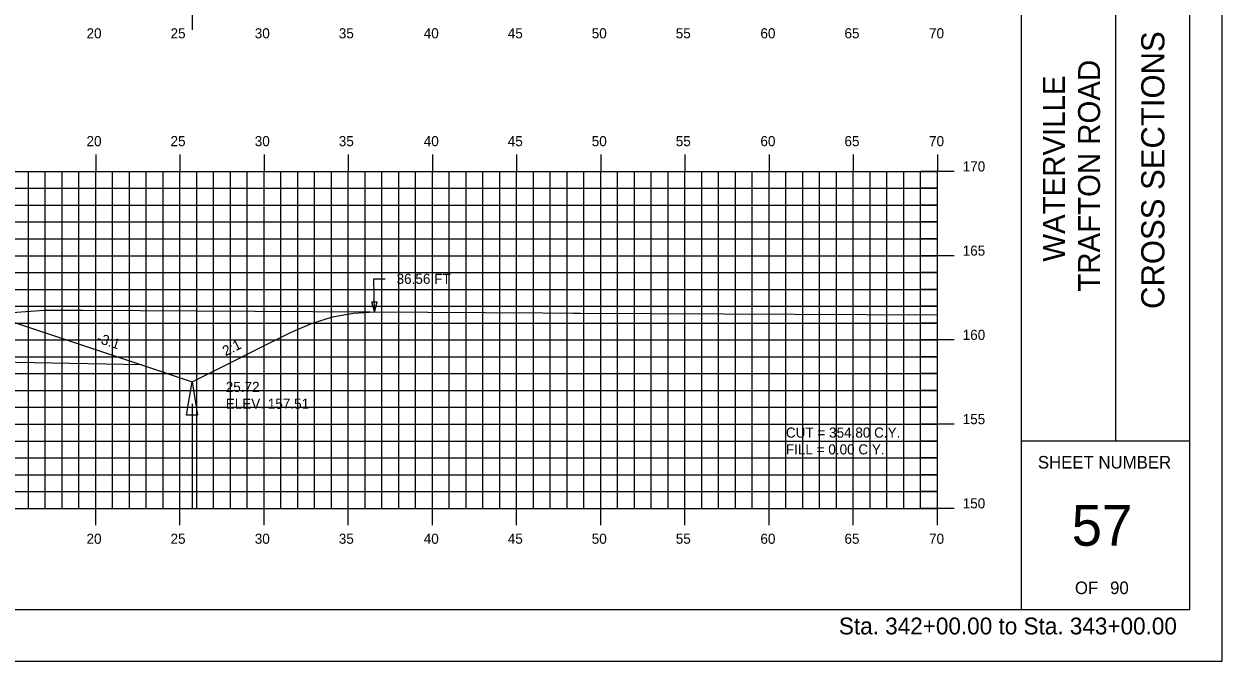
# Model space of a CAD drawing. Extents: x 1143198 to 1143368, y 608981 to 609091.
# Drawn here: x 1143297.1 to 1143368.2, y 608981.3 to 609019.1 of the extents above; entities that cross this region are included whole.
import ezdxf

# ---------------------------------------------------------------- set-up
doc = ezdxf.new("R2010")
doc.units = 0
for name, color, linetype in [('ANNOTATION', 7, 'Continuous'), ('BORDER', 7, 'Continuous'), ('D_Drainage_Ditch_Line', 7, 'Continuous'), ('D_Roadway_SlopeLines', 7, 'Continuous'), ('D_Roadway_SubGrade', 7, 'Continuous'), ('D_Text_Standard', 7, 'Continuous'), ('H_V ANNOTATION', 7, 'Continuous'), ('HIGHWAY_TITLE', 7, 'Continuous'), ('MAJOR', 7, 'Continuous'), ('MINOR', 7, 'Continuous'), ('PLOT BOUNDARY', 7, 'Continuous'), ('S_Roadway_Centerline', 7, 'Continuous')]:
    doc.layers.add(name, color=color, linetype=linetype)

msp = doc.modelspace()

# ---------------------------------------------------------------- linework, layer by layer
msp.add_lwpolyline([(1143243.539, 609002.652), (1143244.789, 609002.562), (1143246.039, 609002.32), (1143247.289, 609001.925), (1143248.539, 609001.376), (1143255.598, 608997.847), (1143258.598, 608998.847), (1143266.322, 609001.421), (1143266.323, 609001.421), (1143270.323, 609001.581), (1143281.323, 609001.801), (1143292.323, 609001.581), (1143296.323, 609001.421), (1143304.047, 608998.847), (1143307.047, 608997.847), (1143312.886, 609000.767), (1143314.136, 609001.313), (1143315.386, 609001.7), (1143316.636, 609001.93), (1143317.886, 609002.001)])
at = {"layer": 'BORDER'}
for p, q in [((1143356.323, 608984.335), (1143356.323, 609089.335)), ((1143361.914, 608994.338), (1143361.914, 609029.338)), ((1143356.323, 608994.338), (1143366.323, 608994.338))]:
    msp.add_line(p, q, dxfattribs=at)
msp.add_lwpolyline([(1143206.323, 608984.335), (1143366.323, 608984.335), (1143366.323, 609089.335), (1143206.323, 609089.335)], close=True, dxfattribs=at)
at = {"layer": 'D_Drainage_Ditch_Line'}
for p, q in [((1143307.047, 609024.984), (1143307.046, 609018.741)), ((1143307.047, 608996.535), (1143307.046, 608990.291))]:
    msp.add_line(p, q, dxfattribs=at)
msp.add_lwpolyline([(1143307.375, 608995.878), (1143306.718, 608995.878), (1143307.047, 608997.847)], close=True, dxfattribs=at)
at = {"layer": 'D_Roadway_SlopeLines'}
for points in [[(1143307.047, 608997.847), (1143312.886, 609000.767), (1143314.136, 609001.313), (1143315.386, 609001.7), (1143316.636, 609001.93), (1143317.886, 609002.001)], [(1143304.047, 608998.847), (1143307.047, 608997.847)]]:
    msp.add_lwpolyline(points, dxfattribs=at)
at = {"layer": 'D_Roadway_SubGrade'}
msp.add_lwpolyline([(1143292.323, 609001.165), (1143292.323, 609001.331), (1143296.323, 609001.171), (1143296.323, 609001.421), (1143296.323, 609001.421), (1143304.047, 608998.847), (1143292.323, 608999.081)], close=True, dxfattribs=at)
at = {"layer": 'D_Text_Standard'}
msp.add_lwpolyline([(1143317.886, 609002.017), (1143317.837, 609003.964), (1143318.517, 609003.964)], dxfattribs=at)
msp.add_lwpolyline([(1143317.886, 609002.017), (1143317.726, 609002.595), (1143318.017, 609002.602)], close=True, dxfattribs=at)
at = {"layer": 'MAJOR'}
for p, q in [((1143301.323, 609011.337), (1143301.323, 609010.335)), ((1143306.323, 609011.337), (1143306.323, 609010.335)), ((1143311.323, 609011.337), (1143311.323, 609010.335)), ((1143316.323, 609011.337), (1143316.323, 609010.335)), ((1143321.323, 609011.337), (1143321.323, 609010.335)), ((1143326.323, 609011.337), (1143326.323, 609010.335)), ((1143331.323, 609011.337), (1143331.323, 609010.335)), ((1143336.323, 609011.337), (1143336.323, 609010.335)), ((1143341.323, 609011.337), (1143341.323, 609010.335)), ((1143346.323, 609011.337), (1143346.323, 609010.335)), ((1143351.323, 609011.337), (1143351.323, 609010.335)), ((1143211.323, 609010.335), (1143351.323, 609010.335)), ((1143211.323, 609010.335), (1143351.323, 609010.335)), ((1143301.323, 608990.335), (1143301.323, 609010.335)), ((1143306.323, 608990.335), (1143306.323, 609010.335)), ((1143311.323, 608990.335), (1143311.323, 609010.335)), ((1143316.323, 608990.335), (1143316.323, 609010.335)), ((1143321.323, 608990.335), (1143321.323, 609010.335)), ((1143326.323, 608990.335), (1143326.323, 609010.335)), ((1143331.323, 608990.335), (1143331.323, 609010.335)), ((1143336.323, 608990.335), (1143336.323, 609010.335)), ((1143341.323, 608990.335), (1143341.323, 609010.335)), ((1143346.323, 608990.335), (1143346.323, 609010.335)), ((1143352.325, 609010.335), (1143350.321, 609010.335)), ((1143351.323, 608990.335), (1143351.323, 609010.335)), ((1143351.323, 608990.335), (1143351.323, 609010.335)), ((1143211.323, 609005.335), (1143351.323, 609005.335)), ((1143352.325, 609005.335), (1143350.321, 609005.335)), ((1143211.323, 609000.335), (1143351.323, 609000.335)), ((1143352.325, 609000.335), (1143350.321, 609000.335)), ((1143211.323, 608995.335), (1143351.323, 608995.335)), ((1143352.325, 608995.335), (1143350.321, 608995.335)), ((1143211.323, 608990.335), (1143351.323, 608990.335)), ((1143211.323, 608990.335), (1143351.323, 608990.335)), ((1143301.323, 608989.333), (1143301.323, 608990.335)), ((1143306.323, 608989.333), (1143306.323, 608990.335)), ((1143311.323, 608989.333), (1143311.323, 608990.335)), ((1143316.323, 608989.333), (1143316.323, 608990.335)), ((1143321.323, 608989.333), (1143321.323, 608990.335)), ((1143326.323, 608989.333), (1143326.323, 608990.335)), ((1143331.323, 608989.333), (1143331.323, 608990.335)), ((1143336.323, 608989.333), (1143336.323, 608990.335)), ((1143341.323, 608989.333), (1143341.323, 608990.335)), ((1143346.323, 608989.333), (1143346.323, 608990.335)), ((1143352.325, 608990.335), (1143350.321, 608990.335)), ((1143351.323, 608989.333), (1143351.323, 608990.335))]:
    msp.add_line(p, q, dxfattribs=at)
at = {"layer": 'MINOR'}
for p, q in [((1143297.323, 608990.335), (1143297.323, 609010.335)), ((1143298.323, 608990.335), (1143298.323, 609010.335)), ((1143299.323, 608990.335), (1143299.323, 609010.335)), ((1143300.323, 608990.335), (1143300.323, 609010.335)), ((1143302.323, 608990.335), (1143302.323, 609010.335)), ((1143303.323, 608990.335), (1143303.323, 609010.335)), ((1143304.323, 608990.335), (1143304.323, 609010.335)), ((1143305.323, 608990.335), (1143305.323, 609010.335)), ((1143307.323, 608990.335), (1143307.323, 609010.335)), ((1143308.323, 608990.335), (1143308.323, 609010.335)), ((1143309.323, 608990.335), (1143309.323, 609010.335)), ((1143310.323, 608990.335), (1143310.323, 609010.335)), ((1143312.323, 608990.335), (1143312.323, 609010.335)), ((1143313.323, 608990.335), (1143313.323, 609010.335)), ((1143314.323, 608990.335), (1143314.323, 609010.335)), ((1143315.323, 608990.335), (1143315.323, 609010.335)), ((1143317.323, 608990.335), (1143317.323, 609010.335)), ((1143318.323, 608990.335), (1143318.323, 609010.335)), ((1143319.323, 608990.335), (1143319.323, 609010.335)), ((1143320.323, 608990.335), (1143320.323, 609010.335)), ((1143322.323, 608990.335), (1143322.323, 609010.335)), ((1143323.323, 608990.335), (1143323.323, 609010.335)), ((1143324.323, 608990.335), (1143324.323, 609010.335)), ((1143325.323, 608990.335), (1143325.323, 609010.335)), ((1143327.323, 608990.335), (1143327.323, 609010.335)), ((1143328.323, 608990.335), (1143328.323, 609010.335)), ((1143329.323, 608990.335), (1143329.323, 609010.335)), ((1143330.323, 608990.335), (1143330.323, 609010.335)), ((1143332.323, 608990.335), (1143332.323, 609010.335)), ((1143333.323, 608990.335), (1143333.323, 609010.335)), ((1143334.323, 608990.335), (1143334.323, 609010.335)), ((1143335.323, 608990.335), (1143335.323, 609010.335)), ((1143337.323, 608990.335), (1143337.323, 609010.335)), ((1143338.323, 608990.335), (1143338.323, 609010.335)), ((1143339.323, 608990.335), (1143339.323, 609010.335)), ((1143340.323, 608990.335), (1143340.323, 609010.335)), ((1143342.323, 608990.335), (1143342.323, 609010.335)), ((1143343.323, 608990.335), (1143343.323, 609010.335)), ((1143344.323, 608990.335), (1143344.323, 609010.335)), ((1143345.323, 608990.335), (1143345.323, 609010.335)), ((1143347.323, 608990.335), (1143347.323, 609010.335)), ((1143348.323, 608990.335), (1143348.323, 609010.335)), ((1143349.323, 608990.335), (1143349.323, 609010.335)), ((1143350.323, 608990.335), (1143350.323, 609010.335)), ((1143211.323, 609009.335), (1143351.323, 609009.335)), ((1143351.323, 609009.335), (1143350.321, 609009.335)), ((1143211.323, 609008.335), (1143351.323, 609008.335)), ((1143351.323, 609008.335), (1143350.321, 609008.335)), ((1143211.323, 609007.335), (1143351.323, 609007.335)), ((1143351.323, 609007.335), (1143350.321, 609007.335)), ((1143211.323, 609006.335), (1143351.323, 609006.335)), ((1143351.323, 609006.335), (1143350.321, 609006.335)), ((1143211.323, 609004.335), (1143351.323, 609004.335)), ((1143351.323, 609004.335), (1143350.321, 609004.335)), ((1143211.323, 609003.335), (1143351.323, 609003.335)), ((1143351.323, 609003.335), (1143350.321, 609003.335)), ((1143211.323, 609002.335), (1143351.323, 609002.335)), ((1143351.323, 609002.335), (1143350.321, 609002.335)), ((1143211.323, 609001.335), (1143351.323, 609001.335)), ((1143351.323, 609001.335), (1143350.321, 609001.335)), ((1143211.323, 608999.335), (1143351.323, 608999.335)), ((1143351.323, 608999.335), (1143350.321, 608999.335)), ((1143211.323, 608998.335), (1143351.323, 608998.335)), ((1143351.323, 608998.335), (1143350.321, 608998.335)), ((1143211.323, 608997.335), (1143351.323, 608997.335)), ((1143351.323, 608997.335), (1143350.321, 608997.335)), ((1143211.323, 608996.335), (1143351.323, 608996.335)), ((1143351.323, 608996.335), (1143350.321, 608996.335)), ((1143211.323, 608994.335), (1143351.323, 608994.335)), ((1143351.323, 608994.335), (1143350.321, 608994.335)), ((1143211.323, 608993.335), (1143351.323, 608993.335)), ((1143351.323, 608993.335), (1143350.321, 608993.335)), ((1143211.323, 608992.335), (1143351.323, 608992.335)), ((1143351.323, 608992.335), (1143350.321, 608992.335)), ((1143211.323, 608991.335), (1143351.323, 608991.335)), ((1143351.323, 608991.335), (1143350.321, 608991.335))]:
    msp.add_line(p, q, dxfattribs=at)
at = {"layer": 'PLOT BOUNDARY'}
msp.add_lwpolyline([(1143198.23, 608981.276), (1143368.23, 608981.276), (1143368.23, 609091.276), (1143198.23, 609091.276)], close=True, dxfattribs=at)
at = {"layer": 'S_Roadway_Centerline'}
msp.add_lwpolyline([(1143295.537, 609001.911), (1143298.268, 609002.095), (1143300.542, 609002.11), (1143327.888, 609001.938), (1143329.7, 609001.93), (1143330.14, 609001.928), (1143351.323, 609001.827)], dxfattribs=at)

# ---------------------------------------------------------------- texts
at = {"layer": 'ANNOTATION'}
for s, rotation, p in [('-3:1', 341.56521, (1143301.334, 609000.205)), ('2:1', 26.56505, (1143309.039, 608999.361))]:
    msp.add_text(s, height=0.6, rotation=rotation, dxfattribs=at).set_placement(p)
at = {"layer": 'BORDER'}
msp.add_text('CROSS SECTIONS', height=1.37787, rotation=90, dxfattribs=at).set_placement((1143364.808, 609002.172))
for s, height, p in [('SHEET NUMBER', 0.74527, (1143357.289, 608992.701)), ('57', 2.4194, (1143359.299, 608988.118)), ('OF', 0.7453, (1143359.49, 608985.248)), ('90', 0.7453, (1143361.58, 608985.248))]:
    msp.add_text(s, height=height, dxfattribs=at).set_placement(p)
at = {"layer": 'D_Text_Standard'}
for s, p in [('36.56 FT', (1143319.197, 609003.664)), ('25.72', (1143309.047, 608997.247)), ('ELEV. 157.51', (1143309.047, 608996.245)), ('CUT = 354.80 C.Y.', (1143342.323, 608994.535)), ('FILL = 0.00 C.Y.', (1143342.323, 608993.539))]:
    msp.add_text(s, height=0.6, dxfattribs=at).set_placement(p)
at = {"layer": 'H_V ANNOTATION'}
for s, height, p in [('20', 0.6, (1143300.777, 609018.235)), ('25', 0.6, (1143305.769, 609018.235)), ('30', 0.6, (1143310.772, 609018.235)), ('35', 0.6, (1143315.764, 609018.235)), ('40', 0.6, (1143320.809, 609018.235)), ('45', 0.6, (1143325.801, 609018.235)), ('50', 0.6, (1143330.788, 609018.235)), ('55', 0.6, (1143335.78, 609018.235)), ('60', 0.6, (1143340.809, 609018.235)), ('65', 0.6, (1143345.801, 609018.235)), ('70', 0.6, (1143350.825, 609018.235)), ('20', 0.6, (1143300.777, 609011.835)), ('25', 0.6, (1143305.769, 609011.835)), ('30', 0.6, (1143310.772, 609011.835)), ('35', 0.6, (1143315.764, 609011.835)), ('40', 0.6, (1143320.809, 609011.835)), ('45', 0.6, (1143325.801, 609011.835)), ('50', 0.6, (1143330.788, 609011.835)), ('55', 0.6, (1143335.78, 609011.835)), ('60', 0.6, (1143340.809, 609011.835)), ('65', 0.6, (1143345.801, 609011.835)), ('70', 0.6, (1143350.825, 609011.835)), ('170', 0.6, (1143352.823, 609010.335)), ('165', 0.6, (1143352.823, 609005.335)), ('160', 0.6, (1143352.823, 609000.335)), ('155', 0.6, (1143352.823, 608995.335)), ('150', 0.6, (1143352.823, 608990.335)), ('20', 0.6, (1143300.777, 608988.235)), ('25', 0.6, (1143305.769, 608988.235)), ('30', 0.6, (1143310.772, 608988.235)), ('35', 0.6, (1143315.764, 608988.235)), ('40', 0.6, (1143320.809, 608988.235)), ('45', 0.6, (1143325.801, 608988.235)), ('50', 0.6, (1143330.788, 608988.235)), ('55', 0.6, (1143335.78, 608988.235)), ('60', 0.6, (1143340.809, 608988.235)), ('65', 0.6, (1143345.801, 608988.235)), ('70', 0.6, (1143350.825, 608988.235)), ('Sta. 342+00.00 to Sta. 343+00.00', 1.0002, (1143345.469, 608982.855))]:
    msp.add_text(s, height=height, dxfattribs=at).set_placement(p)
at = {"layer": 'HIGHWAY_TITLE'}
for s, height, p in [('TRAFTON ROAD', 1.30428, (1143360.983, 609003.201)), ('WATERVILLE', 1.3043, (1143358.896, 609004.98))]:
    msp.add_text(s, height=height, rotation=90, dxfattribs=at).set_placement(p)

doc.saveas('drawing.dxf')
